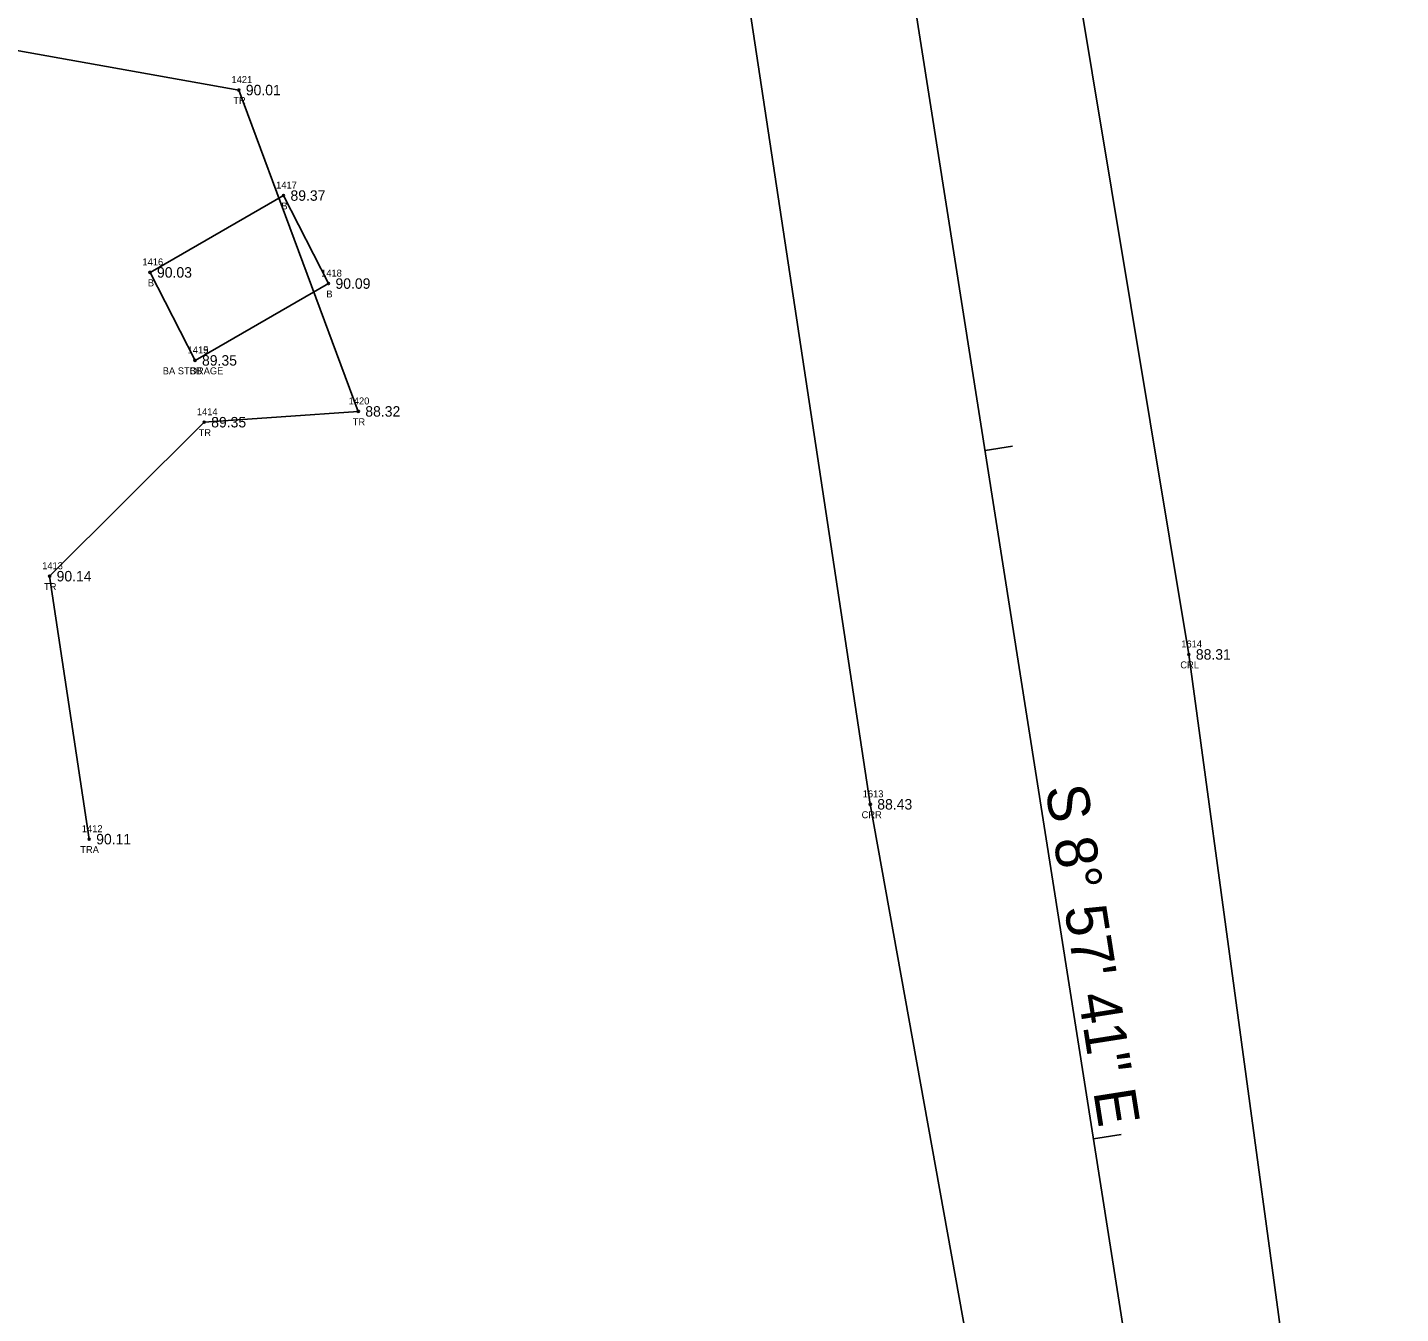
# Model space of a CAD drawing. Extents: x 2529517 to 2532038, y 935000 to 936944.
# Drawn here: x 2531034.4 to 2531231.5, y 935681.4 to 935866 of the extents above; entities that cross this region are included whole.
import ezdxf

# ---------------------------------------------------------------- set-up
doc = ezdxf.new("R2010")
doc.units = 0
for name, color, linetype in [('Default', 7, 'Continuous'), ('RD_EX_Bldg', 7, 'Continuous'), ('RD_EX_Bldg_txCode', 7, 'Continuous'), ('RD_EX_H2O', 7, 'Continuous'), ('RD_EX_H2O_txCode', 7, 'Continuous'), ('RD_EX_TX_Bldg_ELEV', 7, 'Continuous'), ('RD_EX_TX_H2O_ELEV', 7, 'Continuous'), ('RD_EX_TX_VEG_ELEV', 7, 'Continuous'), ('RD_EX_VEG', 7, 'Continuous'), ('RD_EX_VEG_txCode', 7, 'Continuous'), ('RD_HC_Cl', 7, 'Continuous'), ('RD_HC_Data', 7, 'Continuous'), ('RD_HC_Data_Tic', 7, 'Continuous'), ('RD_SMD_Locator', 7, 'Continuous')]:
    doc.layers.add(name, color=color, linetype=linetype)

msp = doc.modelspace()

# ---------------------------------------------------------------- linework, layer by layer
at = {"layer": 'Default'}
msp.add_line((2531158.18, 935892.25), (2531208.86, 935570.87), dxfattribs=at)
at = {"layer": 'RD_EX_Bldg'}
msp.add_lwpolyline([(2531058.5, 935818.17), (2531052.04, 935830.8), (2531071.2, 935841.83), (2531077.66, 935829.2), (2531058.5, 935818.17)], dxfattribs=at)
at = {"layer": 'RD_EX_H2O'}
for points in [[(2531169.61, 936003.09), (2531168.21, 936006.21), (2531167.04, 936004.54), (2531167.21, 936003.45), (2531176, 935975.44), (2531176.84, 935974.76), (2531177.07, 935973.85), (2531179, 935967.11), (2531180.39, 935948.02), (2531175.92, 935941.33), (2531173.5, 935933.2), (2531181.71, 935892.9), (2531201.16, 935775.97), (2531215.24, 935672.42), (2531231.54, 935569.22), (2531229.65, 935447.9)], [(2531078.88, 935952.28), (2531078.96, 935951.18), (2531094.18, 935926.97), (2531103.29, 935929.49), (2531106.67, 935929.67), (2531109.75, 935927.85), (2531109.94, 935928.67), (2531111.53, 935928.19), (2531109.98, 935924.15), (2531114.47, 935921.71), (2531121.2, 935920.45), (2531134.65, 935891.6), (2531155.43, 935754.46), (2531173.73, 935652.91), (2531186.19, 935572.51), (2531201.43, 935446.7)]]:
    msp.add_lwpolyline(points, dxfattribs=at)
at = {"layer": 'RD_EX_VEG'}
msp.add_lwpolyline([(2531043.31, 935749.46), (2531037.63, 935787.2), (2531059.82, 935809.3), (2531081.94, 935810.85), (2531064.79, 935856.97), (2531020.07, 935864.93), (2531018.25, 935872.47), (2531057.21, 935896.36), (2531092.01, 935912.12), (2531117.32, 935919.34)], dxfattribs=at)
at = {"layer": 'RD_HC_Cl'}
msp.add_line((2531158.18, 935892.25), (2531208.86, 935570.87), dxfattribs=at)
at = {"layer": 'RD_HC_Data_Tic'}
for p, q in [((2531171.9, 935805.24), (2531175.85, 935805.87)), ((2531187.48, 935706.46), (2531191.43, 935707.09))]:
    msp.add_line(p, q, dxfattribs=at)
at = {"layer": 'RD_SMD_Locator'}
for centre in [(2531064.79, 935856.97), (2531071.2, 935841.83), (2531052.04, 935830.8), (2531077.66, 935829.2), (2531058.5, 935818.17), (2531058.5, 935818.17), (2531081.94, 935810.85), (2531059.82, 935809.3), (2531037.63, 935787.2), (2531201.16, 935775.97), (2531155.43, 935754.46), (2531043.31, 935749.46)]:
    msp.add_circle(centre, 0.15, dxfattribs=at)

# ---------------------------------------------------------------- texts
at = {"layer": 'RD_EX_Bldg_txCode'}
for s, p in [('1417', (2531070.14, 935842.83)), ('B', (2531070.89, 935839.83)), ('1416', (2531050.95, 935831.8)), ('B', (2531051.73, 935828.8)), ('1418', (2531076.6, 935830.2)), ('B', (2531077.35, 935827.2)), ('1419', (2531057.44, 935819.17)), ('1415', (2531057.44, 935819.17)), ('BA STORAGE', (2531053.87, 935816.17)), ('BB', (2531057.72, 935816.17))]:
    msp.add_text(s, height=1, dxfattribs=at).set_placement(p)
at = {"layer": 'RD_EX_H2O_txCode'}
for s, p in [('1614', (2531200.07, 935776.97)), ('CRL', (2531199.93, 935773.97)), ('1613', (2531154.34, 935755.46)), ('CRR', (2531154.18, 935752.46))]:
    msp.add_text(s, height=1, dxfattribs=at).set_placement(p)
at = {"layer": 'RD_EX_TX_Bldg_ELEV'}
for s, p in [('89.37', (2531072.2, 935841.08)), ('90.03', (2531053.04, 935830.05)), ('90.09', (2531078.66, 935828.45)), ('89.35', (2531059.5, 935817.42)), ('89.35', (2531059.5, 935817.42))]:
    msp.add_text(s, height=1.5, dxfattribs=at).set_placement(p)
at = {"layer": 'RD_EX_TX_H2O_ELEV'}
for s, p in [('88.31', (2531202.16, 935775.22)), ('88.43', (2531156.43, 935753.71))]:
    msp.add_text(s, height=1.5, dxfattribs=at).set_placement(p)
at = {"layer": 'RD_EX_TX_VEG_ELEV'}
for s, p in [('90.01', (2531065.79, 935856.22)), ('88.32', (2531082.94, 935810.1)), ('89.35', (2531060.82, 935808.55)), ('90.14', (2531038.63, 935786.45)), ('90.11', (2531044.31, 935748.71))]:
    msp.add_text(s, height=1.5, dxfattribs=at).set_placement(p)
at = {"layer": 'RD_EX_VEG_txCode'}
for s, p in [('1421', (2531063.73, 935857.97)), ('TR', (2531064, 935854.97)), ('1420', (2531080.55, 935811.85)), ('1414', (2531058.76, 935810.3)), ('TR', (2531059.02, 935807.3)), ('TR', (2531081.14, 935808.85)), ('1413', (2531036.56, 935788.2)), ('TR', (2531036.83, 935785.2)), ('1412', (2531042.25, 935750.46)), ('TRA', (2531042.03, 935747.46))]:
    msp.add_text(s, height=1, dxfattribs=at).set_placement(p)
at = {"layer": 'RD_HC_Data'}
msp.add_text('S 8%%d 57\' 41" E', height=6, rotation=278.9613, dxfattribs=at).set_placement((2531180.55, 935756.84))

doc.saveas('drawing.dxf')
